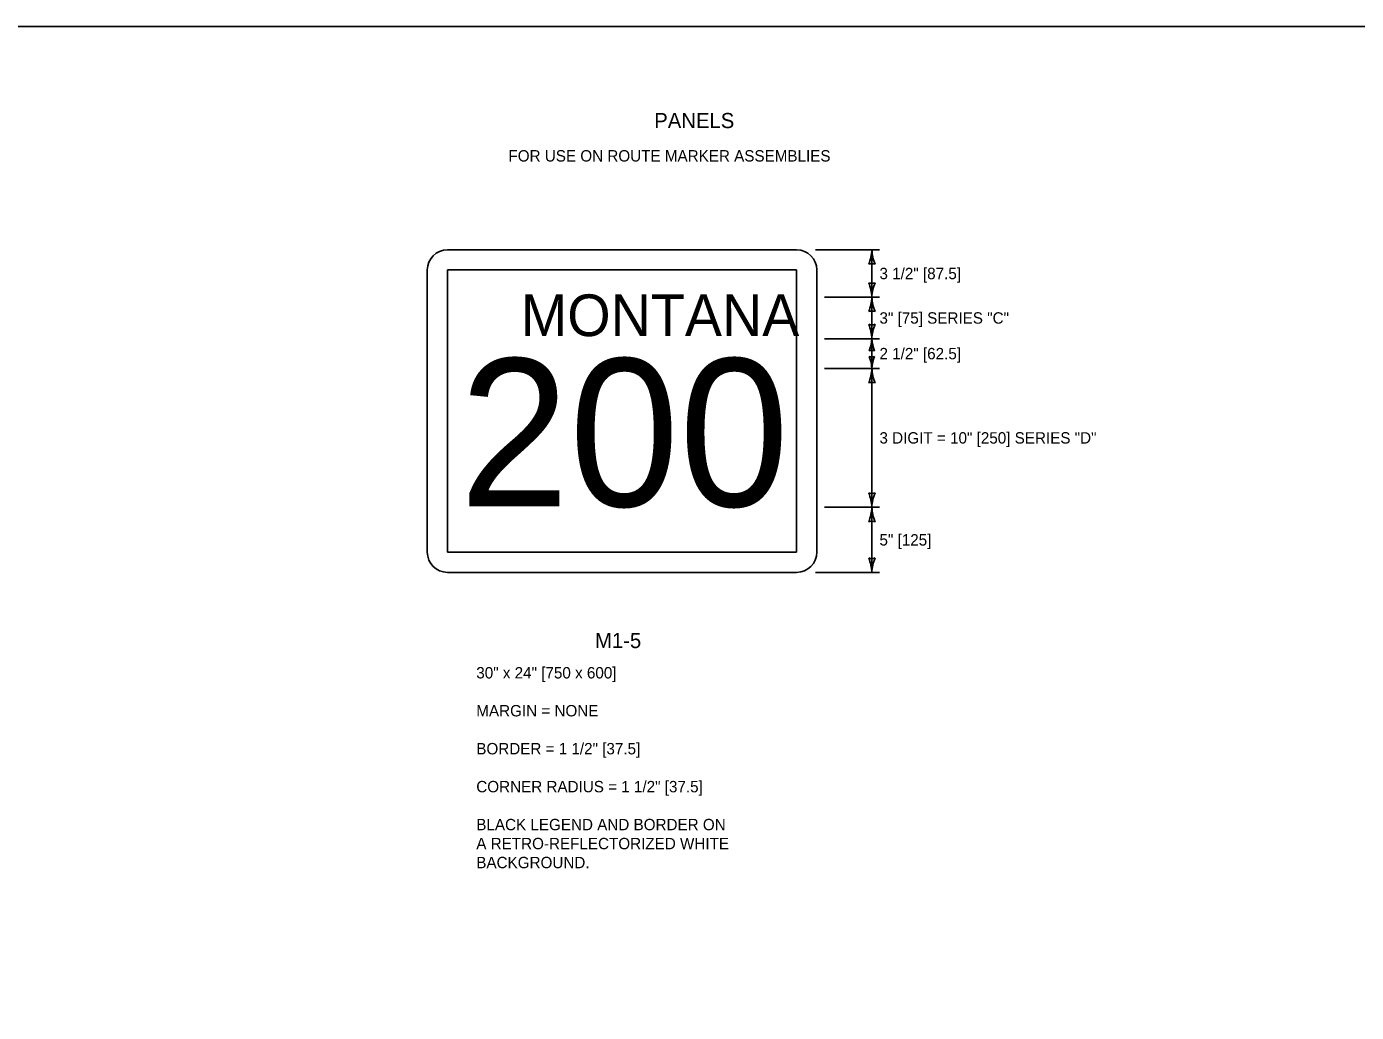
# Model space of a CAD drawing. Extents: x 49991.4 to 50021, y 49987.6 to 50011.4.
# Drawn here: x 50004.53 to 50011.55, y 49993.8 to 49999 of the extents above; entities that cross this region are included whole.
import ezdxf

# ---------------------------------------------------------------- set-up
doc = ezdxf.new("R2010")
doc.units = 0
for name, color, linetype in [('Level 1', 7, 'Continuous'), ('Level 2', 7, 'Continuous'), ('Level 3', 7, 'Continuous')]:
    doc.layers.add(name, color=color, linetype=linetype)

msp = doc.modelspace()

# ---------------------------------------------------------------- linework, layer by layer
at = {"layer": 'Level 1'}
for p, q in [((50006.7516, 49997.823), (50008.5932, 49997.823)), ((50006.6453, 49996.2293), (50006.6453, 49997.7168)), ((50006.7516, 49996.2293), (50006.7516, 49997.7168)), ((50006.7516, 49997.7168), (50008.5932, 49997.7168)), ((50008.5932, 49997.7168), (50008.5932, 49996.2293)), ((50008.6994, 49997.7168), (50008.6994, 49996.2293)), ((50008.5932, 49996.2293), (50006.7516, 49996.2293)), ((50008.5932, 49996.123), (50006.7516, 49996.123))]:
    msp.add_line(p, q, dxfattribs=at)
msp.add_lwpolyline([(49999.3835, 49998.9992), (50016.7501, 49998.9992), (50016.7501, 49987.7988), (49999.3835, 49987.7988)], close=True, dxfattribs=at)
for centre, start, end in [((50006.7516, 49997.7168), 90, 180), ((50008.5932, 49997.7168), 0, 90), ((50006.7516, 49996.2293), 180, 270), ((50008.5932, 49996.2293), 270, 0)]:
    msp.add_arc(centre, 0.1063, start, end, dxfattribs=at)
at = {"layer": 'Level 3'}
for p, q in [((50008.6932, 49997.823), (50009.03, 49997.823)), ((50008.99, 49997.823), (50008.99, 49997.5734)), ((50008.7394, 49997.5734), (50009.03, 49997.5734)), ((50008.99, 49997.5734), (50008.99, 49997.3543)), ((50008.7394, 49997.3543), (50009.03, 49997.3543)), ((50008.99, 49997.3543), (50008.99, 49997.1978)), ((50008.7394, 49997.1978), (50009.03, 49997.1978)), ((50008.99, 49997.1978), (50008.99, 49996.466)), ((50008.7394, 49996.466), (50009.03, 49996.466)), ((50008.99, 49996.466), (50008.99, 49996.123)), ((50008.6932, 49996.123), (50009.03, 49996.123))]:
    msp.add_line(p, q, dxfattribs=at)
for centre, radius, start, end in [((50008.7679, 49997.8322), 0.2223, 337.45601, 357.63952), ((50009.2227, 49997.8345), 0.233, 182.82731, 202.07716), ((50008.99, 49997.6948), 0.0548, 72.13882, 107.86118), ((50008.99, 49997.7016), 0.0548, 252.13882, 287.86118), ((50008.7573, 49997.5619), 0.233, 2.82731, 22.07716), ((50009.2121, 49997.5642), 0.2223, 157.45601, 177.63952), ((50008.7679, 49997.5826), 0.2223, 337.45601, 357.63952), ((50009.2227, 49997.5849), 0.233, 182.82731, 202.07716), ((50008.99, 49997.4452), 0.0548, 72.13882, 107.86118), ((50008.99, 49997.4825), 0.0548, 252.13882, 287.86118), ((50008.7573, 49997.3428), 0.233, 2.82731, 22.07716), ((50009.2121, 49997.3451), 0.2223, 157.45601, 177.63952), ((50008.8049, 49997.3619), 0.1853, 337.45601, 357.63952), ((50009.1839, 49997.3639), 0.1942, 182.82731, 202.07716), ((50008.99, 49997.2475), 0.0456, 72.13882, 107.86118), ((50008.7679, 49997.207), 0.2223, 337.45601, 357.63952), ((50008.99, 49997.3046), 0.0456, 252.13882, 287.86118), ((50008.7961, 49997.1882), 0.1942, 2.82731, 22.07716), ((50009.1751, 49997.1902), 0.1853, 157.45601, 177.63952), ((50009.2227, 49997.2093), 0.233, 182.82731, 202.07716), ((50008.99, 49997.0696), 0.0548, 72.13882, 107.86118), ((50008.99, 49996.5942), 0.0548, 252.13882, 287.86118), ((50008.7573, 49996.4545), 0.233, 2.82731, 22.07716), ((50009.2121, 49996.4568), 0.2223, 157.45601, 177.63952), ((50008.7679, 49996.4752), 0.2223, 337.45601, 357.63952), ((50009.2227, 49996.4775), 0.233, 182.82731, 202.07716), ((50008.99, 49996.3378), 0.0548, 72.13882, 107.86118), ((50008.99, 49996.2512), 0.0548, 252.13882, 287.86118), ((50008.7573, 49996.1115), 0.233, 2.82731, 22.07716), ((50009.2121, 49996.1138), 0.2223, 157.45601, 177.63952)]:
    msp.add_arc(centre, radius, start, end, dxfattribs=at)

# ---------------------------------------------------------------- texts
at = {"layer": 'Level 1'}
for s, height, p in [('MONTANA', 0.2196, (50007.1391, 49997.3683)), ('200', 0.7791, (50006.8149, 49996.4705))]:
    msp.add_text(s, height=height, dxfattribs=at).set_placement(p)
at = {"layer": 'Level 2'}
for s, height, p in [('PANELS', 0.08, (50007.8422, 49998.4642)), ('FOR USE ON ROUTE MARKER ASSEMBLIES', 0.06, (50007.0734, 49998.2882)), ('3 1/2" [87.5]', 0.06, (50009.03, 49997.6682)), ('3" [75] SERIES "C"', 0.06, (50009.03, 49997.4338)), ('2 1/2" [62.5]', 0.06, (50009.03, 49997.246)), ('3 DIGIT = 10" [250] SERIES "D"', 0.06, (50009.03, 49996.8019)), ('5" [125]', 0.06, (50009.03, 49996.2645)), ('M1-5', 0.08, (50007.5298, 49995.7241)), ('30" x 24" [750 x 600]', 0.06, (50006.9038, 49995.5641)), ('MARGIN = NONE', 0.06, (50006.9038, 49995.3641)), ('BORDER = 1 1/2" [37.5]', 0.06, (50006.9038, 49995.1641)), ('CORNER RADIUS = 1 1/2" [37.5]', 0.06, (50006.9038, 49994.9641)), ('BLACK LEGEND AND BORDER ON ', 0.06, (50006.9038, 49994.7641)), ('A RETRO-REFLECTORIZED WHITE ', 0.06, (50006.9038, 49994.6641)), ('BACKGROUND.', 0.06, (50006.9038, 49994.5641))]:
    msp.add_text(s, height=height, dxfattribs=at).set_placement(p)

doc.saveas('drawing.dxf')
